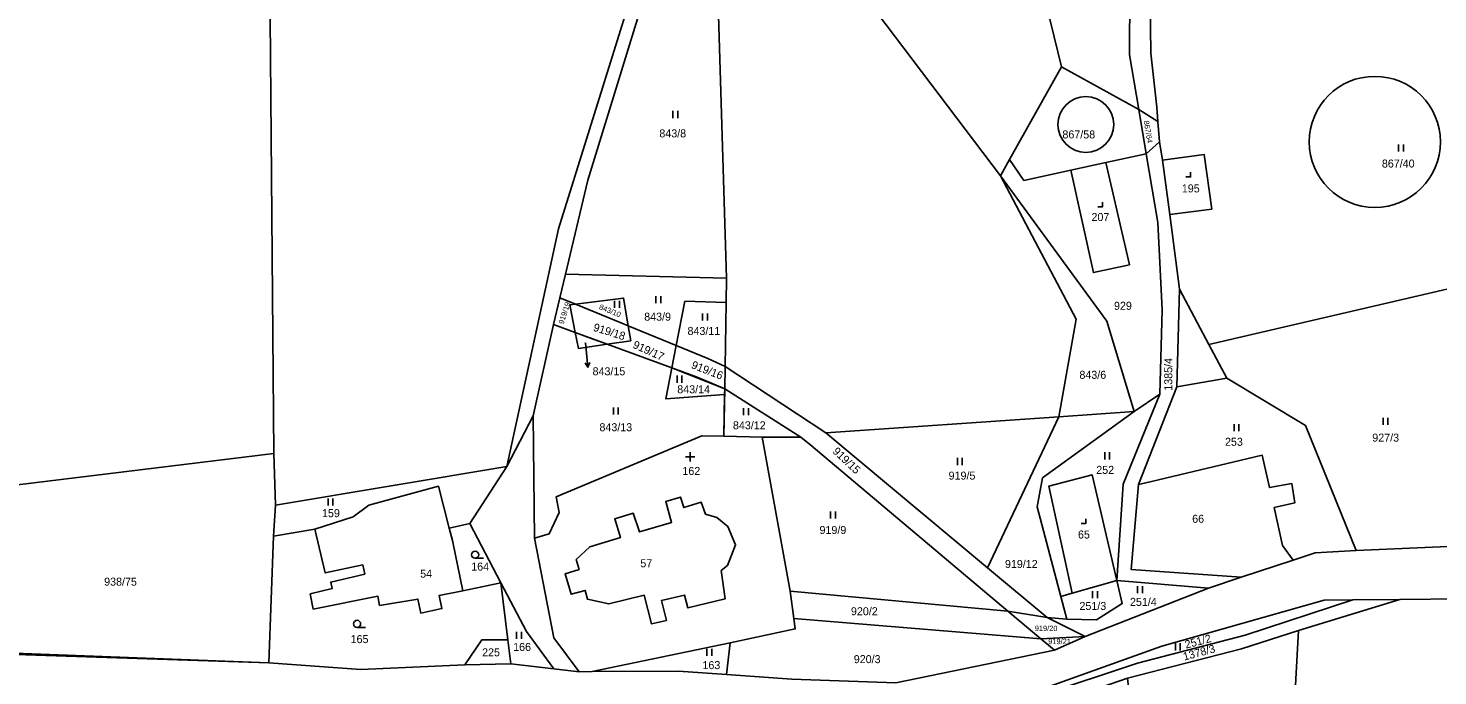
# Model space of a CAD drawing. Extents: x -588699 to -585793, y -1060280 to -1056731.
# Drawn here: x -588120.4 to -587820.9, y -1058115.3 to -1057977.7 of the extents above; entities that cross this region are included whole.
import ezdxf

# ---------------------------------------------------------------- set-up
doc = ezdxf.new("R2010")
doc.units = 0
for name, color, linetype in [('Druh pozemku', 7, 'Continuous'), ('Lesy', 7, 'Continuous'), ('Parcela nároku', 7, 'Continuous'), ('Parcelní číslo', 7, 'Continuous'), ('Změna katastrální hranice', 7, 'Continuous')]:
    doc.layers.add(name, color=color, linetype=linetype)

msp = doc.modelspace()

# ---------------------------------------------------------------- linework, layer by layer
at = {"layer": 'Druh pozemku'}
for p, q in [((-587983.46, -1057995.28), (-587983.46, -1057996.78)), ((-587982.44, -1057996.78), (-587982.44, -1057995.28)), ((-587829.28, -1058002.4), (-587829.28, -1058003.9)), ((-587828.26, -1058003.9), (-587828.26, -1058002.4)), ((-587987.07, -1058034.6), (-587987.07, -1058036.1)), ((-587986.05, -1058036.1), (-587986.05, -1058034.6)), ((-587995.86, -1058035.61), (-587995.86, -1058037.11)), ((-587994.83, -1058037.11), (-587994.83, -1058035.61)), ((-587977.14, -1058038.3), (-587977.14, -1058039.8)), ((-587976.11, -1058039.8), (-587976.11, -1058038.3)), ((-587982.57, -1058051.52), (-587982.57, -1058053.02)), ((-587981.55, -1058053.02), (-587981.55, -1058051.52)), ((-587996.09, -1058058.3), (-587996.09, -1058059.8)), ((-587995.07, -1058059.8), (-587995.07, -1058058.3)), ((-587968.44, -1058058.4), (-587968.44, -1058059.9)), ((-587967.42, -1058059.9), (-587967.42, -1058058.4)), ((-587864.24, -1058061.84), (-587864.24, -1058063.34)), ((-587863.21, -1058063.34), (-587863.21, -1058061.84)), ((-587832.55, -1058060.47), (-587832.55, -1058061.97)), ((-587831.53, -1058061.97), (-587831.53, -1058060.47)), ((-587979.78, -1058067.79), (-587979.78, -1058069.79)), ((-587891.69, -1058067.81), (-587891.69, -1058069.31)), ((-587890.67, -1058069.31), (-587890.67, -1058067.81)), ((-587980.78, -1058068.79), (-587978.78, -1058068.79)), ((-587923.02, -1058069.01), (-587923.02, -1058070.51)), ((-587921.99, -1058070.51), (-587921.99, -1058069.01)), ((-588056.69, -1058077.61), (-588056.69, -1058079.11)), ((-588055.67, -1058079.11), (-588055.67, -1058077.61)), ((-587949.96, -1058080.39), (-587949.96, -1058081.89)), ((-587948.94, -1058081.89), (-587948.94, -1058080.39)), ((-588023.72, -1058090.32), (-588025.47, -1058090.32)), ((-587894.3, -1058097.29), (-587894.3, -1058098.79)), ((-587893.28, -1058098.79), (-587893.28, -1058097.29)), ((-587884.73, -1058096.22), (-587884.73, -1058097.72)), ((-587883.7, -1058097.72), (-587883.7, -1058096.22)), ((-588048.8, -1058105.01), (-588050.55, -1058105.01)), ((-588016.65, -1058105.94), (-588016.65, -1058107.44)), ((-588015.62, -1058107.44), (-588015.62, -1058105.94)), ((-587976.22, -1058109.55), (-587976.22, -1058111.05)), ((-587975.2, -1058111.05), (-587975.2, -1058109.55)), ((-587876.71, -1058108.4), (-587876.71, -1058109.9)), ((-587875.69, -1058109.9), (-587875.69, -1058108.4))]:
    msp.add_line(p, q, dxfattribs=at)
for points in [[(-587874.46, -1058009.3), (-587873.46, -1058009.3), (-587873.46, -1058008.3)], [(-587893.16, -1058015.62), (-587892.16, -1058015.62), (-587892.16, -1058014.62)], [(-587896.7, -1058082.91), (-587895.7, -1058082.91), (-587895.7, -1058081.91)]]:
    msp.add_lwpolyline(points, dxfattribs=at)
for centre in [(-588025.47, -1058089.57), (-588050.55, -1058104.26)]:
    msp.add_circle(centre, 0.75, dxfattribs=at)
at = {"layer": 'Lesy'}
for p, q in [((-588013.12, -1058060.06), (-588008.85, -1058040.67)), ((-588008.85, -1058040.67), (-588004.19, -1058042.37)), ((-588004.19, -1058042.37), (-587997.41, -1058044.85)), ((-587997.41, -1058044.85), (-587983.66, -1058049.86)), ((-587983.66, -1058049.86), (-587972.45, -1058054.35)), ((-587876.37, -1058053.92), (-587865.8, -1058052.07)), ((-587865.8, -1058052.07), (-587849.09, -1058062.13)), ((-588018.76, -1058070.8), (-588013.12, -1058060.06)), ((-587849.09, -1058062.13), (-587838.26, -1058088.66)), ((-587964.49, -1058064.58), (-587958.56, -1058097.3)), ((-588026.59, -1058082.94), (-588018.76, -1058070.8)), ((-588048.08, -1058079.05), (-588033.28, -1058075.01)), ((-588033.28, -1058075.01), (-588030.98, -1058083.9)), ((-588051.42, -1058081.49), (-588048.08, -1058079.05)), ((-588059.51, -1058084.13), (-588051.42, -1058081.49)), ((-588030.98, -1058083.9), (-588026.59, -1058082.94)), ((-588069.32, -1058112.52), (-588068.33, -1058085.63)), ((-588068.33, -1058085.63), (-588059.51, -1058084.13)), ((-587838.26, -1058088.66), (-587817.22, -1058087.77)), ((-587958.56, -1058097.3), (-587912.28, -1058101.55)), ((-587912.28, -1058101.55), (-587903.95, -1058102.92)), ((-587903.95, -1058102.92), (-587895.86, -1058106.98)), ((-588130.29, -1058110.23), (-588069.32, -1058112.52))]:
    msp.add_line(p, q, dxfattribs=at)
for points in [[(-587972.45, -1058054.35), (-587972.6, -1058064.4), (-587964.49, -1058064.58)], [(-587895.86, -1058106.98), (-587869.7, -1058096.65), (-587862.71, -1058094.35), (-587886.07, -1058092.72), (-587884.54, -1058074.67), (-587876.37, -1058053.92)]]:
    msp.add_lwpolyline(points, dxfattribs=at)
at = {"layer": 'Parcela nároku'}
for points in [[(-587998.57, -1057617.58), (-587998.64, -1057610.93), (-588083.68, -1057635.65), (-588081.67, -1057721.71), (-588069.75, -1057891.27), (-588068.25, -1058068.03), (-588067.88, -1058079.03), (-588018.76, -1058070.8), (-588007.76, -1058020.32), (-587988.03, -1057956.92), (-587980.59, -1057925.6), (-587982.76, -1057925.42), (-587984.09, -1057917.75), (-587989.35, -1057910.25), (-587982.46, -1057891.11), (-587981.97, -1057875.19), (-587984.13, -1057845.06), (-587987.3, -1057805.85), (-587992.29, -1057757.6), (-587992.48, -1057712.96)], [(-588146.85, -1057654), (-588083.68, -1057635.65), (-588081.67, -1057721.71), (-588069.75, -1057891.27), (-588068.25, -1058068.03), (-588129.14, -1058075.51), (-588132.27, -1058023.47), (-588130.87, -1057996.67), (-588127.55, -1057944.29), (-588127.1, -1057903.81), (-588141.26, -1057786.74), (-588142.09, -1057762.75), (-588146.38, -1057724.97)], [(-587913.54, -1057933.95), (-587900.93, -1057985.93), (-587911.91, -1058005.56), (-587913.87, -1058009.06), (-587939.9, -1057974.61), (-587953.32, -1057956.49), (-587964.15, -1057939.99), (-587916.62, -1057921.23), (-587915.79, -1057924.66)], [(-587986.08, -1057959.78), (-588001.51, -1058009.97), (-588006.28, -1058029.92), (-587972.09, -1058030.78), (-587975.24, -1057925.95), (-587977.79, -1057926.08)], [(-587787.01, -1057976), (-587780.16, -1057998.87), (-587781.12, -1058000.9), (-587778.11, -1058005.58), (-587765.81, -1058045.87), (-587784.84, -1058048.59), (-587789.52, -1058033.22), (-587813.41, -1058035.08), (-587812.97, -1058031.76), (-587869.58, -1058044.93), (-587875.83, -1058033.11), (-587877.91, -1058017.26), (-587868.98, -1058016.13), (-587870.56, -1058004.56), (-587879.42, -1058005.73), (-587880.07, -1058001.83), (-587880.42, -1057997.53), (-587880.67, -1057994.5), (-587881.93, -1057982.97), (-587882.18, -1057961.3), (-587814.02, -1057942.82), (-587813.68, -1057985.91), (-587810.98, -1057985.75), (-587805.91, -1057973.34)], [(-587911.91, -1058005.56), (-587908.89, -1058010.02), (-587898.9, -1058007.85), (-587891.5, -1058006.24), (-587882.93, -1058004.38), (-587884.5, -1057994.99), (-587900.93, -1057985.93)], [(-587884.5, -1057994.99), (-587882.93, -1058004.38), (-587880.07, -1058001.83), (-587880.42, -1057997.53)], [(-587877.91, -1058017.26), (-587879.42, -1058005.73), (-587880.07, -1058001.83), (-587882.93, -1058004.38), (-587880.46, -1058018.94), (-587879.53, -1058037.51), (-587880, -1058055.45), (-587887.76, -1058074.55), (-587889.13, -1058095.07), (-587869.7, -1058096.65), (-587862.71, -1058094.35), (-587886.07, -1058092.72), (-587884.54, -1058074.67), (-587876.37, -1058053.92), (-587875.83, -1058033.11)], [(-587879.53, -1058037.51), (-587880.46, -1058018.94), (-587882.93, -1058004.38), (-587891.5, -1058006.24), (-587886.48, -1058027.97), (-587894.1, -1058029.62), (-587898.9, -1058007.85), (-587908.89, -1058010.02), (-587911.91, -1058005.56), (-587913.87, -1058009.06), (-587891.27, -1058039.92), (-587885.45, -1058059.14), (-587880, -1058055.45)], [(-587868.98, -1058016.13), (-587877.91, -1058017.26), (-587879.42, -1058005.73), (-587870.56, -1058004.56)], [(-587886.48, -1058027.97), (-587891.5, -1058006.24), (-587898.9, -1058007.85), (-587894.1, -1058029.62)], [(-587897.78, -1058039.53), (-587901.45, -1058060.25), (-587885.45, -1058059.14), (-587891.27, -1058039.92), (-587913.87, -1058009.06)], [(-588007.49, -1058035), (-588006.28, -1058029.92), (-587972.09, -1058030.78), (-587972.17, -1058035.98), (-587980.92, -1058035.7), (-587982.74, -1058045.1), (-587992.94, -1058040.94), (-587993.94, -1058035.03), (-588004.18, -1058036.35)], [(-587813.41, -1058035.08), (-587812.97, -1058031.76), (-587869.58, -1058044.93), (-587865.8, -1058052.07), (-587849.09, -1058062.13), (-587838.26, -1058088.66), (-587817.22, -1058087.77), (-587816.69, -1058059.91)], [(-588004.18, -1058036.35), (-588007.49, -1058035), (-588008.85, -1058040.67), (-588004.19, -1058042.37), (-588005.36, -1058036.5)], [(-587992.94, -1058040.94), (-587993.94, -1058035.03), (-588004.18, -1058036.35), (-587994.33, -1058040.37)], [(-587849.09, -1058062.13), (-587865.8, -1058052.07), (-587869.58, -1058044.93), (-587875.83, -1058033.11), (-587876.37, -1058053.92), (-587884.54, -1058074.67), (-587881.75, -1058074.01), (-587858.25, -1058068.42), (-587856.7, -1058075.31), (-587851.97, -1058074.44), (-587851.32, -1058078.53), (-587855.74, -1058079.57), (-587853.92, -1058087.64), (-587851.65, -1058090.72), (-587846.97, -1058089.18), (-587838.26, -1058088.66)], [(-587994.33, -1058040.37), (-587992.94, -1058040.94), (-587992.41, -1058044.1), (-587997.41, -1058044.85), (-588000.99, -1058043.54), (-588004.19, -1058042.37), (-588005.36, -1058036.5), (-588004.18, -1058036.35)], [(-587982.74, -1058045.1), (-587980.92, -1058035.7), (-587972.17, -1058035.98), (-587972.38, -1058049.6), (-587976.01, -1058047.85)], [(-587972.47, -1058055.49), (-587972.6, -1058064.4), (-587977.29, -1058064.3), (-588008.23, -1058077.24), (-588007.6, -1058080.58), (-588009.73, -1058085.11), (-588012.85, -1058086.07), (-588013.12, -1058060.06), (-588008.85, -1058040.67), (-588004.19, -1058042.37), (-588003.51, -1058045.76), (-587997.41, -1058044.85), (-587983.66, -1058049.86), (-587984.94, -1058056.48)], [(-587992.94, -1058040.94), (-587982.74, -1058045.1), (-587983.66, -1058049.86), (-587997.41, -1058044.85), (-587992.41, -1058044.1)], [(-587997.41, -1058044.85), (-588000.99, -1058043.54), (-588004.19, -1058042.37), (-588003.51, -1058045.76)], [(-587972.38, -1058049.6), (-587976.01, -1058047.85), (-587982.74, -1058045.1), (-587983.66, -1058049.86), (-587978.33, -1058051.81), (-587972.45, -1058054.35)], [(-587972.47, -1058055.49), (-587972.45, -1058054.35), (-587978.33, -1058051.81), (-587983.66, -1058049.86), (-587984.94, -1058056.48)], [(-587972.38, -1058049.6), (-587950.96, -1058063.67), (-587916.61, -1058092.35), (-587903.95, -1058102.92), (-587912.28, -1058101.55), (-587954.09, -1058066.36), (-587956.3, -1058064.58), (-587972.45, -1058054.35)], [(-587956.3, -1058064.58), (-587972.45, -1058054.35), (-587972.47, -1058055.49), (-587972.6, -1058064.4), (-587964.49, -1058064.58)], [(-587904.94, -1058073.24), (-587906.05, -1058079.43), (-587901.02, -1058098.44), (-587898.63, -1058097.76), (-587903.61, -1058075.03), (-587894.41, -1058072.56), (-587889.13, -1058095.07), (-587887.76, -1058074.55), (-587880, -1058055.45), (-587885.45, -1058059.14)], [(-587916.61, -1058092.35), (-587903.95, -1058102.92), (-587899.75, -1058103.26), (-587901.02, -1058098.44), (-587906.05, -1058079.43), (-587904.94, -1058073.24), (-587885.45, -1058059.14), (-587901.45, -1058060.25)], [(-587901.45, -1058060.25), (-587950.96, -1058063.67), (-587916.61, -1058092.35)], [(-587972.6, -1058064.4), (-587977.29, -1058064.3), (-588008.23, -1058077.24), (-588007.6, -1058080.58), (-588009.73, -1058085.11), (-588012.85, -1058086.07), (-588008.73, -1058107.2), (-588003.37, -1058114.43), (-588000.59, -1058114.37), (-587971.28, -1058108.32), (-587957.46, -1058105.34), (-587957.76, -1058103.14), (-587958.56, -1058097.3), (-587964.49, -1058064.58)], [(-587956.3, -1058064.58), (-587954.09, -1058066.36), (-587912.28, -1058101.55), (-587958.56, -1058097.3), (-587964.49, -1058064.58)], [(-588068.25, -1058068.03), (-588067.88, -1058079.03), (-588068.33, -1058085.63), (-588069.32, -1058112.52), (-588129.61, -1058110.55), (-588130.29, -1058110.23), (-588129.14, -1058075.51)], [(-588068.33, -1058085.63), (-588067.88, -1058079.03), (-588018.76, -1058070.8), (-588026.59, -1058082.94), (-588030.98, -1058083.9), (-588033.28, -1058075.01), (-588048.08, -1058079.05), (-588051.42, -1058081.49), (-588059.51, -1058084.13)], [(-587853.92, -1058087.64), (-587851.65, -1058090.72), (-587862.71, -1058094.35), (-587886.07, -1058092.72), (-587884.54, -1058074.67), (-587881.75, -1058074.01), (-587858.25, -1058068.42), (-587856.7, -1058075.31), (-587851.97, -1058074.44), (-587851.32, -1058078.53), (-587855.74, -1058079.57)], [(-587889.13, -1058095.07), (-587894.41, -1058072.56), (-587903.61, -1058075.03), (-587898.63, -1058097.76)], [(-588059.51, -1058084.13), (-588051.42, -1058081.49), (-588048.08, -1058079.05), (-588033.28, -1058075.01), (-588030.98, -1058083.9), (-588030.29, -1058086.56), (-588028.12, -1058097.21), (-588033.1, -1058098.23), (-588032.53, -1058101.02), (-588037.02, -1058101.98), (-588037.64, -1058098.99), (-588045.77, -1058100.34), (-588046.14, -1058098.4), (-588059.87, -1058101.12), (-588060.5, -1058097.89), (-588055.83, -1058096.73), (-588056.16, -1058095.37), (-588048.91, -1058093.68), (-588049.36, -1058091.75), (-588057.33, -1058093.45)], [(-587974.09, -1058081.64), (-587971.77, -1058083.54), (-587970.14, -1058087.46), (-587971.87, -1058091.85), (-587973.23, -1058092.95), (-587972.35, -1058098.92), (-587980.27, -1058100.87), (-587980.96, -1058098.16), (-587985.86, -1058099.33), (-587984.85, -1058103.54), (-587987.98, -1058104.27), (-587989.54, -1058098.17), (-587997.06, -1058100.03), (-588001.6, -1058099.02), (-588002.13, -1058097.15), (-588005.06, -1058097.98), (-588006.32, -1058093.6), (-588003.38, -1058092.73), (-588003.98, -1058090.6), (-588001.09, -1058087.88), (-587994.6, -1058085.94), (-587995.81, -1058081.92), (-587991.87, -1058080.75), (-587990.57, -1058084.74), (-587983.72, -1058082.7), (-587984.96, -1058078.28), (-587981.81, -1058077.33), (-587981.14, -1058079.54), (-587977.44, -1058078.41), (-587976.56, -1058080.97)], [(-587971.87, -1058091.85), (-587973.23, -1058092.95), (-587972.35, -1058098.92), (-587980.27, -1058100.87), (-587980.96, -1058098.16), (-587985.86, -1058099.33), (-587984.85, -1058103.54), (-587987.98, -1058104.27), (-587989.54, -1058098.17), (-587997.06, -1058100.03), (-588001.6, -1058099.02), (-588002.13, -1058097.15), (-588005.06, -1058097.98), (-588006.32, -1058093.6), (-588003.38, -1058092.73), (-588003.98, -1058090.6), (-588001.09, -1058087.88), (-587994.6, -1058085.94), (-587995.81, -1058081.92), (-587991.87, -1058080.75), (-587990.57, -1058084.74), (-587983.72, -1058082.7), (-587984.96, -1058078.28), (-587981.81, -1058077.33), (-587981.14, -1058079.54), (-587977.44, -1058078.41), (-587976.56, -1058080.97), (-587974.09, -1058081.64), (-587971.77, -1058083.54), (-587970.14, -1058087.46)], [(-588019.99, -1058095.55), (-588026.59, -1058082.94), (-588030.98, -1058083.9), (-588030.29, -1058086.56), (-588028.12, -1058097.21)], [(-588069.32, -1058112.52), (-588068.33, -1058085.63), (-588059.51, -1058084.13), (-588057.33, -1058093.45), (-588049.36, -1058091.75), (-588048.91, -1058093.68), (-588056.16, -1058095.37), (-588055.83, -1058096.73), (-588060.5, -1058097.89), (-588059.87, -1058101.12), (-588046.14, -1058098.4), (-588045.77, -1058100.34), (-588037.64, -1058098.99), (-588037.02, -1058101.98), (-588032.53, -1058101.02), (-588033.1, -1058098.23), (-588028.12, -1058097.21), (-588019.99, -1058095.55), (-588018.51, -1058107.68), (-588024.08, -1058107.68), (-588027.63, -1058113), (-588049.75, -1058113.96)], [(-587899.75, -1058103.26), (-587893.44, -1058103.43), (-587887.98, -1058099.97), (-587889.13, -1058095.07), (-587869.7, -1058096.65), (-587895.86, -1058106.98), (-587903.95, -1058102.92)], [(-587889.13, -1058095.07), (-587898.63, -1058097.76), (-587901.02, -1058098.44), (-587899.75, -1058103.26), (-587893.44, -1058103.43), (-587887.98, -1058099.97)], [(-588014.59, -1058105.87), (-588008.77, -1058113.8), (-588017.89, -1058112.74), (-588018.51, -1058107.68), (-588019.99, -1058095.55)], [(-587905.27, -1058107.44), (-587912.28, -1058101.55), (-587958.56, -1058097.3), (-587957.76, -1058103.14)], [(-587829.03, -1058099.08), (-587838.98, -1058099.18), (-587861.9, -1058106.68), (-587884.72, -1058112.59), (-587905.41, -1058119.52), (-587910.22, -1058119.99), (-587919.57, -1058124.47), (-587907.12, -1058122.2), (-587904.74, -1058121.73), (-587890.55, -1058117.09), (-587886.86, -1058115.78), (-587862.63, -1058109.57), (-587850.57, -1058105.64)], [(-587879.59, -1058109.01), (-587910.22, -1058119.99), (-587905.41, -1058119.52), (-587884.72, -1058112.59), (-587861.9, -1058106.68), (-587838.98, -1058099.18), (-587845.09, -1058099.24)], [(-587850.57, -1058105.64), (-587829.03, -1058099.08), (-587815.92, -1058098.95), (-587814.88, -1058124.25), (-587817.73, -1058158.68), (-587829.62, -1058159.17), (-587827.97, -1058122.42), (-587851.39, -1058121.17)], [(-587905.27, -1058107.44), (-587957.76, -1058103.14), (-587957.46, -1058105.34), (-587971.28, -1058108.32), (-587972.07, -1058115), (-587958.19, -1058116.05), (-587936.11, -1058116.81), (-587902.41, -1058109.85)], [(-587912.28, -1058101.55), (-587903.95, -1058102.92), (-587895.86, -1058106.98), (-587905.27, -1058107.44)], [(-587905.27, -1058107.44), (-587895.86, -1058106.98), (-587902.41, -1058109.85)], [(-587869.72, -1058158.8), (-587871.89, -1058121.72), (-587851.39, -1058121.17), (-587850.57, -1058105.64), (-587862.63, -1058109.57), (-587886.86, -1058115.78), (-587884.63, -1058136.73), (-587886.03, -1058156.97)], [(-588018.51, -1058107.68), (-588024.08, -1058107.68), (-588027.63, -1058113), (-588017.89, -1058112.74)], [(-587971.28, -1058108.32), (-588000.59, -1058114.37), (-587982.29, -1058114.31), (-587972.07, -1058115)]]:
    msp.add_lwpolyline(points, close=True, dxfattribs=at)
for points in [[(-587989.27, -1057759.84), (-587975.36, -1057891.18), (-587977.79, -1057926.08), (-587986.08, -1057959.78), (-588001.51, -1058009.97), (-588006.28, -1058029.92), (-588007.49, -1058035), (-588008.85, -1058040.67), (-588013.12, -1058060.06), (-588012.85, -1058086.07), (-588008.73, -1058107.2), (-588003.37, -1058114.43), (-588008.77, -1058113.8), (-588014.59, -1058105.87), (-588019.99, -1058095.55), (-588026.59, -1058082.94), (-588018.76, -1058070.8), (-588007.76, -1058020.32), (-587988.03, -1057956.92), (-587980.59, -1057925.6), (-587978.66, -1057894.49), (-587980.15, -1057873.46), (-587984.13, -1057845.06), (-587987.3, -1057805.85)], [(-587902.37, -1057798.19), (-587898.85, -1057825.76), (-587892.79, -1057843.76), (-587885.17, -1057883.85), (-587880.28, -1057913.57), (-587882.18, -1057961.3), (-587881.93, -1057982.97), (-587880.67, -1057994.5), (-587880.42, -1057997.53), (-587884.5, -1057994.99), (-587886.46, -1057983.33), (-587886.34, -1057956.6), (-587884.58, -1057914.16), (-587896.7, -1057842.78), (-587902.17, -1057825.76), (-587905.69, -1057797.41)], [(-587975.24, -1057925.95), (-587972.09, -1058030.78), (-587972.17, -1058035.98), (-587972.38, -1058049.6), (-587950.96, -1058063.67), (-587901.45, -1058060.25), (-587897.78, -1058039.53), (-587913.87, -1058009.06), (-587939.9, -1057974.61)], [(-587913.54, -1057933.95), (-587900.93, -1057985.93), (-587884.5, -1057994.99), (-587886.46, -1057983.33), (-587886.34, -1057956.6)], [(-588289.55, -1058135.97), (-588283.37, -1058098.3), (-588283.01, -1058096.11), (-588282.73, -1058094.39), (-588275.87, -1058089.04), (-588268.33, -1058083.17), (-588249.06, -1058081.13), (-588198.72, -1058092.12), (-588135.81, -1058108.15), (-588134.39, -1058108.31), (-588130.29, -1058110.23), (-588129.61, -1058110.55), (-588069.32, -1058112.52), (-588049.75, -1058113.96), (-588027.63, -1058113), (-588017.89, -1058112.74), (-588008.77, -1058113.8), (-588003.37, -1058114.43), (-588000.59, -1058114.37), (-587982.29, -1058114.31), (-587972.07, -1058115), (-587958.19, -1058116.05)], [(-587936.11, -1058116.81), (-587902.41, -1058109.85), (-587895.86, -1058106.98), (-587869.7, -1058096.65), (-587862.71, -1058094.35), (-587851.65, -1058090.72), (-587846.97, -1058089.18), (-587838.26, -1058088.66), (-587817.22, -1058087.77)], [(-587815.92, -1058098.95), (-587829.03, -1058099.08), (-587838.98, -1058099.18), (-587845.09, -1058099.24), (-587879.59, -1058109.01), (-587910.22, -1058119.99)]]:
    msp.add_lwpolyline(points, dxfattribs=at)
at = {"layer": 'Parcelní číslo'}
for p, q in [((-588002.05, -1058044.55), (-588001.82, -1058046.76)), ((-588001.82, -1058046.76), (-588001.52, -1058049.74))]:
    msp.add_line(p, q, dxfattribs=at)
msp.add_lwpolyline([(-588001.12, -1058048.7), (-588001.52, -1058049.74), (-588002.11, -1058048.8)], dxfattribs=at)
at = {"layer": 'Změna katastrální hranice'}
for centre, radius in [((-587834.33, -1058001.85), 13.93), ((-587895.73, -1057998.15), 5.93)]:
    msp.add_circle(centre, radius, dxfattribs=at)

# ---------------------------------------------------------------- texts
at = {"layer": 'Parcela nároku'}
for s, height, p in [('843/8', 1.7, (-587986.33, -1058000.89)), ('867/58', 1.7, (-587900.7, -1058001.11)), ('867/40', 1.7, (-587832.83, -1058007.3)), ('195', 1.7, (-587875.33, -1058012.58)), ('207', 1.7, (-587894.53, -1058018.66)), ('843/9', 1.7, (-587989.55, -1058039.84)), ('929', 1.7, (-587889.74, -1058037.52)), ('843/11', 1.7, (-587980.35, -1058042.87)), ('843/15', 0.1, (-588002.25, -1058044.55)), ('843/6', 1.7, (-587897.09, -1058052.19)), ('843/14', 1.7, (-587982.53, -1058055.27)), ('843/13', 1.7, (-587999.06, -1058063.33)), ('843/12', 1.7, (-587970.7, -1058062.92)), ('253', 1.7, (-587866.16, -1058066.42)), ('927/3', 1.7, (-587834.87, -1058065.54)), ('162', 1.7, (-587981.44, -1058072.62)), ('252', 1.7, (-587893.51, -1058072.39)), ('919/5', 1.7, (-587924.88, -1058073.61)), ('159', 1.7, (-588058, -1058081.59)), ('66', 1.7, (-587873.13, -1058082.78)), ('919/9', 1.7, (-587952.31, -1058085.17)), ('65', 1.7, (-587897.39, -1058086.13)), ('164', 1.7, (-588026.3, -1058092.94)), ('57', 1.7, (-587990.37, -1058092.24)), ('919/12', 1.7, (-587912.91, -1058092.39)), ('938/75', 1.7, (-588104.29, -1058096.15)), ('54', 1.7, (-588037.15, -1058094.45)), ('920/2', 1.7, (-587945.63, -1058102.43)), ('251/3', 1.7, (-587897.08, -1058101.31)), ('251/4', 1.7, (-587886.35, -1058100.44)), ('165', 1.7, (-588051.93, -1058108.35)), ('919/20', 1.14, (-587906.57, -1058105.79)), ('225', 1.7, (-588023.99, -1058111.16)), ('166', 1.7, (-588017.39, -1058110.02)), ('919/21', 1.14, (-587903.72, -1058108.57)), ('163', 1.7, (-587977.18, -1058113.88)), ('920/3', 1.7, (-587945.03, -1058112.61))]:
    msp.add_text(s, height=height, dxfattribs=at).set_placement(p)
for s, height, rotation, p in [('867/64', 1.14, 279.518, (-587883.44, -1057997.42)), ('919/19', 1.14, 72.3239, (-588006.69, -1058040.67)), ('843/10', 1.14, 337.6844, (-587999.25, -1058037.34)), ('919/18', 1.7, 342.6568, (-588000.52, -1058041.95)), ('919/17', 1.7, 335.6719, (-587992.13, -1058045.54)), ('919/16', 1.7, 338.6543, (-587979.69, -1058049.88)), ('1385/4', 1.7, 90, (-587877.36, -1058054.72)), ('919/15', 1.7, 316.5383, (-587949.66, -1058067.77)), ('251/2', 1.7, 14.84, (-587874.44, -1058109.54)), ('1378/3', 1.7, 15.0705, (-587874.82, -1058112.08))]:
    msp.add_text(s, height=height, rotation=rotation, dxfattribs=at).set_placement(p)
at = {"layer": 'Parcelní číslo'}
msp.add_text('843/15', height=1.7, dxfattribs=at).set_placement((-588000.52, -1058051.44))

doc.saveas('drawing.dxf')
